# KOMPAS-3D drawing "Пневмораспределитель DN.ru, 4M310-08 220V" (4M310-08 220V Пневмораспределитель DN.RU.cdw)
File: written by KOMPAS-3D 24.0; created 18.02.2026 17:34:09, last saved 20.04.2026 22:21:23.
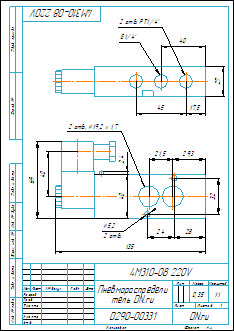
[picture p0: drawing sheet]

Document properties: Автор: R2D2; Форматы листов документа: A4; Полное имя файла: 4M310-08 220V Пневмораспределитель DN.RU.m3d; Масса: 0.35; Наименование: Пневмораспределитель DN.ru; Количество листов документа: 1; Примечание: D290-00331

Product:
- Part/product: Пневмораспределитель DN.ru  | designation 4M310-08 220V
    Масса: 0.35
    Раздел спецификации: Прочие изделия
    Примечание: D290-00331

Views: Вид 1, Спереди, Проекционный вид 2
Referenced files in E:\Работа\Зайцев\Аксессуары для пневмоприводов\Пневмораспределители DN.ru\4М310-08 NAMUR Пневмораспределитель DN.RU\4М310-08 24VDC NAMUR Пневмораспределитель DN.RU\: 4M310-08 24VDC Пневмораспределитель DN.ru.m3d
Referenced files in E:\Работа\Зайцев\Аксессуары для пневмоприводов\Пневмораспределители DN.ru\4М310-08 NAMUR Пневмораспределитель DN.RU\4M310-08 220V NAMUR Пневмораспределитель DN.RU\: 4M310-08 220V Пневмораспределитель DN.RU.m3d
Referenced files in E:\Работа\Зайцев\Для компаса\: чертеж DN.ru.cdt
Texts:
  чертеж DN.ru.cdt
  Пневмораспредели
  тель DN.ru
  Пневмораспределитель DN.ru
  4M310-08 220V Пневмораспределитель DN.ru
Dimensions and other numbers on the sheet: 0; 3; 2; 4; 2 отв. PT1/4'; 27; 40; 17,5; 45; 4M310-08 220V; 69; 24; 28; 32; 29,3; 21,5; 135; 2,4; 5,2; 2 отв.; 2 отв.  19,2 х 1,7; 1:1; 1; 0,35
